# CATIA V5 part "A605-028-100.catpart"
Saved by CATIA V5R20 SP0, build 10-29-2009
Part number: A605-028-100
Source: Unknown
Property "A": "0.000"
Property "ARTICLENO": "A605-028-100"
Property "BOMINFO": "A605-028-100"
Property "CODE": "A605-028-100"
Property "D": "9.000"
Property "FORM": "A"
Property "L": "100.000"
Property "L1": "70.000"
Property "LINA": "A605-028-100"
Property "NB": "A605-028-100"
Property "NBSYN": "$CODE."
Property "NN": "A605"
Property "NT": "Wear Plates, self-lubricating"
Property "SCREW": "2*M8X16"
Property "SUPPLIER": "CF"
Property "W": "28.000"
Bounding box of the stored display mesh (mm): x -28 to 0, y 0 to 5, z -100 to 0
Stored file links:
  C:\Users\Utente\Desktop\3D files A605\A605-028-100.catpart
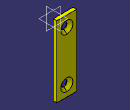
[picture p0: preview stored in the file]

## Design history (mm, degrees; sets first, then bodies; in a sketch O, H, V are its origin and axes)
Body1 "Geometry.1" (main body)
  Solid1 "A605-028-100.catpart": solid without history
